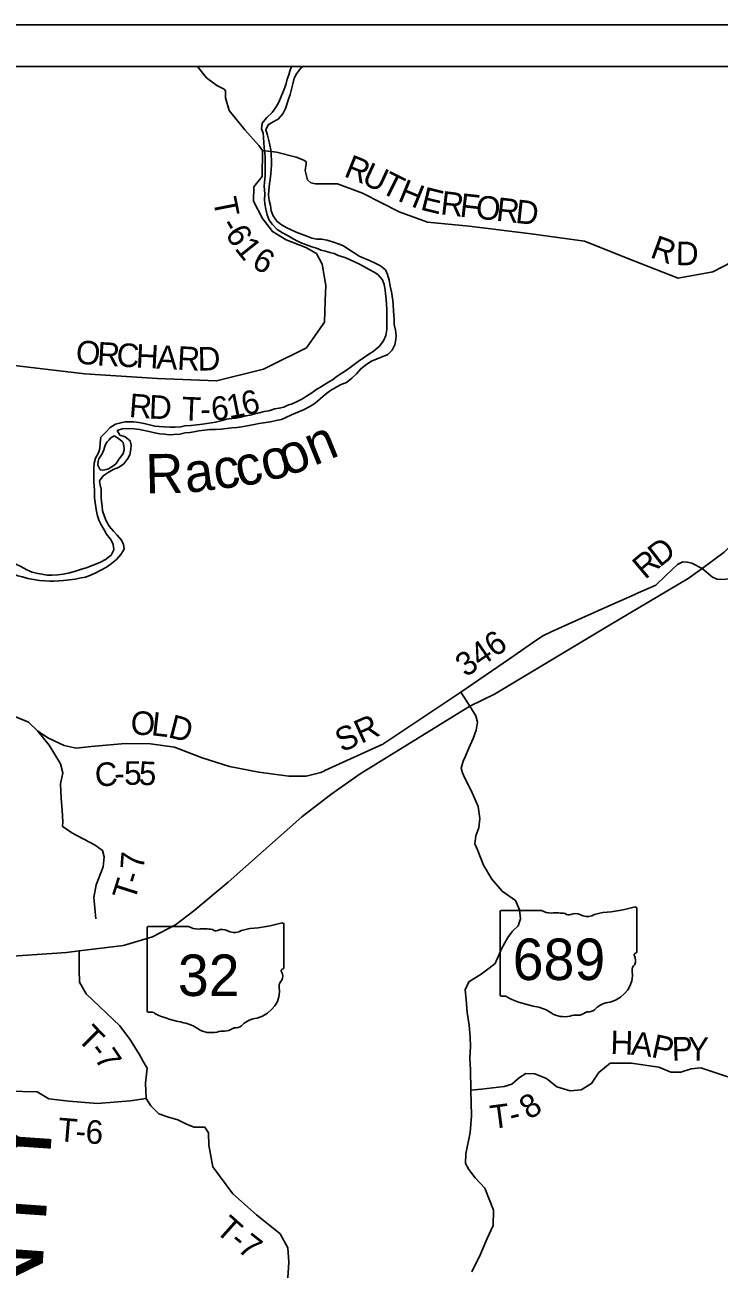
# Model space of a CAD drawing. Extents: x -15 to 405, y -40 to 87.
# Drawn here: x 1.031 to 2.706, y -21.816 to -18.816 of the extents above; entities that cross this region are included whole.
import ezdxf

# ---------------------------------------------------------------- set-up
doc = ezdxf.new("R2010")
doc.units = 0
for name, color, linetype in [('GM_P_State_Alignment', 7, 'Continuous'), ('GM_P_State_Location', 7, 'Continuous'), ('GM_X_Major_Lake_Text', 7, 'Continuous'), ('GM_X_Minor_Lake', 7, 'Continuous'), ('GM_X_Minor_River', 7, 'Continuous'), ('GM_X_State_Location', 7, 'Continuous'), ('GM_X_Township', 7, 'Continuous'), ('GM_X_Township_Road', 7, 'Continuous'), ('GM_X_Township_Road_Text', 7, 'Continuous'), ('GM_X_Township_Subdivision', 7, 'Continuous'), ('GM_X_Township_Text', 7, 'Continuous')]:
    doc.layers.add(name, color=color, linetype=linetype)

msp = doc.modelspace()

# ---------------------------------------------------------------- linework, layer by layer
at = {"layer": 'GM_P_State_Location'}
for points in [[(1.4474, -18.9161), (1.4694, -18.944), (1.4941, -18.9626), (1.5114, -18.9709), (1.5136, -18.9726), (1.5146, -18.9747), (1.5153, -18.9782), (1.5146, -18.9922), (1.5237, -19.0226), (1.5614, -19.0689), (1.5956, -19.1068), (1.6044, -19.1187), (1.6377, -19.1227), (1.6856, -19.1353), (1.7038, -19.1421), (1.7092, -19.1459), (1.7095, -19.1508), (1.7073, -19.1675), (1.713, -19.1895), (1.7208, -19.1966), (1.7323, -19.199), (1.7855, -19.199), (1.8452, -19.2221), (1.934, -19.2669), (2.0024, -19.2915), (2.1031, -19.3013), (2.2523, -19.3199), (2.3814, -19.3376), (2.5, -19.3847), (2.6071, -19.4267), (2.691, -19.4115), (2.7369, -19.3872)], [(1.7554, -19.481), (1.7554, -19.4808), (1.7568, -19.4447), (1.748, -19.3927), (1.7343, -19.3676), (1.7085, -19.3528), (1.661, -19.3342), (1.628, -19.3145), (1.6044, -19.283), (1.5824, -19.2409), (1.5831, -19.2063), (1.6036, -19.182), (1.6044, -19.1187)], [(0.9536, -19.6152), (0.9852, -19.635), (1.1759, -19.6577), (1.351, -19.6686), (1.493, -19.6742), (1.6065, -19.6464), (1.6212, -19.6391)], [(1.2021, -20.9712), (1.1972, -20.9196), (1.2032, -20.8892), (1.2199, -20.8462), (1.2225, -20.8223), (1.218, -20.8064), (1.2009, -20.7938), (1.1443, -20.7643), (1.1303, -20.7547), (1.122, -20.7487), (1.1222, -20.7377), (1.1211, -20.7096), (1.1188, -20.6815), (1.1172, -20.6458), (1.1229, -20.6196), (1.1172, -20.5976), (1.0895, -20.5528), (1.0625, -20.5186)], [(1.3135, -21.3097), (1.3133, -21.3093), (1.3064, -21.2974), (1.2855, -21.2636), (1.26, -21.229), (1.1791, -21.152), (1.1627, -21.1243), (1.1623, -21.0943), (1.1621, -21.0489)], [(1.6592, -21.9368), (1.6675, -21.7993), (1.6656, -21.7643), (1.6466, -21.7309), (1.5899, -21.6854), (1.5326, -21.6345), (1.4847, -21.5692), (1.4744, -21.5172), (1.4736, -21.4876), (1.4652, -21.4739), (1.4497, -21.4739), (1.439, -21.4739), (1.4208, -21.4667), (1.4003, -21.4557), (1.3771, -21.45), (1.354, -21.4413), (1.335, -21.4219), (1.3236, -21.4049), (1.322, -21.3673), (1.3262, -21.3316), (1.3135, -21.3097)], [(2.1066, -21.3846), (2.1328, -21.382), (2.1871, -21.3755), (2.2057, -21.3698), (2.2239, -21.3538), (2.2395, -21.3447), (2.2608, -21.3454), (2.2892, -21.356), (2.3143, -21.3762), (2.3466, -21.3864), (2.3732, -21.3841), (2.3982, -21.3681), (2.4157, -21.3419), (2.4426, -21.3191), (2.4935, -21.3195), (2.5604, -21.3293), (2.5896, -21.3411), (2.6132, -21.341), (2.6382, -21.3334), (2.6614, -21.3308), (2.7879, -21.3721)], [(0.8359, -21.4075), (0.8808, -21.4017), (0.9525, -21.3865), (1.0608, -21.3883), (1.0885, -21.4054), (1.1371, -21.4114), (1.2062, -21.4167), (1.2848, -21.4102), (1.3236, -21.4049)]]:
    msp.add_lwpolyline(points, dxfattribs=at)
at = {"layer": 'GM_X_Major_Lake_Text'}
msp.add_lwpolyline([(1.6212, -19.6391), (1.6228, -19.6383), (1.7102, -19.5947), (1.7534, -19.5328), (1.7554, -19.481)], dxfattribs=at)
at = {"layer": 'GM_X_State_Location'}
for points in [[(2.1043, -20.4588), (2.1641, -20.4294), (2.4411, -20.2634), (2.6314, -20.1512), (2.6648, -20.1267), (2.7182, -20.0876), (2.7981, -20.0074), (2.8513, -19.9357)], [(0.8594, -21.0713), (1.1313, -21.0528), (1.1621, -21.0489), (1.2686, -21.0355), (1.3387, -21.0145), (1.3944, -20.9859), (1.4388, -20.9525), (1.521, -20.8829), (1.6991, -20.7258), (1.7688, -20.6714), (1.8396, -20.6216), (2.1043, -20.4588)], [(2.0929, -20.5809), (2.0929, -20.5809), (2.1023, -20.5603), (2.1126, -20.537), (2.1199, -20.5167), (2.1232, -20.4974), (2.1188, -20.4823), (2.1043, -20.4588)], [(2.1095, -21.8225), (2.1299, -21.7798), (2.1462, -21.7424), (2.1606, -21.7111), (2.1613, -21.6739), (2.1405, -21.6209), (2.1171, -21.5961), (2.1017, -21.5758), (2.0939, -21.5611), (2.0951, -21.5379), (2.1055, -21.4869), (2.1085, -21.4467), (2.1066, -21.3846), (2.1057, -21.3358), (2.1042, -21.3062), (2.1061, -21.2789), (2.1051, -21.2565), (2.1025, -21.2277), (2.0976, -21.1973), (2.0953, -21.1659), (2.0931, -21.1427), (2.102, -21.1233), (2.1314, -21.1047), (2.151, -21.09), (2.1653, -21.0793), (2.1816, -21.0422), (2.1961, -21.0163), (2.2073, -21.0013), (2.2212, -20.9883), (2.2263, -20.9715), (2.2242, -20.9495), (2.2148, -20.9276), (2.1822, -20.9048), (2.1576, -20.8759), (2.1375, -20.8419), (2.1226, -20.8053), (2.1167, -20.7909), (2.1192, -20.7711), (2.1258, -20.7517), (2.1289, -20.7293), (2.1244, -20.7005), (2.108, -20.6623), (2.0925, -20.6325), (2.0866, -20.6193), (2.0831, -20.6079), (2.0882, -20.5912), (2.0929, -20.5809)]]:
    msp.add_lwpolyline(points, dxfattribs=at)
at = {"layer": 'GM_X_Township'}
for p, q in [((-0.7646, -18.8161), (6.2354, -18.8161)), ((-0.6646, -18.9161), (6.1354, -18.9161)), ((-0.6646, -18.9161), (6.1354, -18.9161))]:
    msp.add_line(p, q, dxfattribs=at)
at = {"layer": 'GM_X_Township_Road'}
for points in [[(1.6739, -18.9161), (1.6701, -18.9273), (1.6675, -18.9368), (1.6641, -18.9466), (1.6615, -18.9573), (1.6581, -18.9668), (1.6536, -18.9789), (1.6495, -18.9884), (1.6438, -19.0021), (1.637, -19.0138), (1.6272, -19.0275), (1.6144, -19.0397), (1.603, -19.053), (1.6019, -19.0666), (1.6061, -19.0769), (1.6069, -19.0867), (1.6073, -19.0996), (1.6085, -19.1125), (1.61, -19.125), (1.6104, -19.1348), (1.6104, -19.1474), (1.6108, -19.1599), (1.6109, -19.1803), (1.6094, -19.1951), (1.6083, -19.2046), (1.6087, -19.2141), (1.6095, -19.2239), (1.6091, -19.238), (1.6099, -19.2474), (1.6126, -19.2607), (1.6156, -19.274), (1.6202, -19.2868), (1.6274, -19.2967), (1.6399, -19.3095), (1.6525, -19.3175), (1.6661, -19.325), (1.6778, -19.3318), (1.6885, -19.3375), (1.6994, -19.3424), (1.7101, -19.3465), (1.7229, -19.3514), (1.7347, -19.3544), (1.746, -19.3589), (1.7559, -19.3615), (1.7669, -19.3645), (1.7771, -19.3675), (1.787, -19.3721), (1.8029, -19.3773), (1.8139, -19.3815), (1.826, -19.3871), (1.8362, -19.3924), (1.8487, -19.3988)], [(1.9006, -19.4066), (1.8888, -19.3972), (1.8763, -19.3904), (1.8642, -19.3847), (1.8377, -19.3734), (1.8256, -19.3655), (1.8127, -19.358), (1.7994, -19.3489), (1.7895, -19.3448), (1.7755, -19.3399), (1.76, -19.335), (1.7467, -19.3327), (1.735, -19.3324), (1.7236, -19.3305), (1.7115, -19.3253), (1.6986, -19.3207), (1.6858, -19.3155), (1.6721, -19.3094), (1.6626, -19.3053), (1.6501, -19.2985), (1.6384, -19.2894), (1.6296, -19.2762), (1.6251, -19.2645), (1.6232, -19.2516), (1.6201, -19.2395), (1.6189, -19.2266), (1.6193, -19.2148), (1.6212, -19.1996), (1.6226, -19.1886), (1.6245, -19.1754), (1.6249, -19.164), (1.6256, -19.1534), (1.626, -19.1431), (1.6252, -19.1303), (1.624, -19.1174), (1.6194, -19.0946), (1.616, -19.0818), (1.6122, -19.0693), (1.6182, -19.0567), (1.6303, -19.0499), (1.642, -19.043), (1.653, -19.0308), (1.6597, -19.0179), (1.6631, -19.0084), (1.6673, -18.9955), (1.671, -18.9838), (1.6774, -18.958), (1.6808, -18.9447), (1.6864, -18.9337), (1.6959, -18.9212), (1.7014, -18.9161)], [(1.8487, -19.3988), (1.8616, -19.4056), (1.8733, -19.412), (1.8828, -19.418), (1.8935, -19.4309), (1.898, -19.4423), (1.9003, -19.4551), (1.9011, -19.4646), (1.9023, -19.4767), (1.9034, -19.4904), (1.9038, -19.5014), (1.9042, -19.515), (1.9043, -19.5507), (1.9017, -19.5651), (1.896, -19.578), (1.8855, -19.5913), (1.8715, -19.6038), (1.8609, -19.6103), (1.8348, -19.6278), (1.822, -19.637), (1.8095, -19.6468), (1.7959, -19.6556), (1.7842, -19.6632), (1.7728, -19.672), (1.7615, -19.6784), (1.7468, -19.6876), (1.7328, -19.6963), (1.7229, -19.7032), (1.7105, -19.7116), (1.7006, -19.7177), (1.6859, -19.7253), (1.6757, -19.7299), (1.6655, -19.7333), (1.6556, -19.7379), (1.6443, -19.7398), (1.6341, -19.7421), (1.6193, -19.7463), (1.6083, -19.7486), (1.5962, -19.7513), (1.5856, -19.7536), (1.5743, -19.7567), (1.5637, -19.759), (1.5516, -19.7617), (1.5402, -19.764), (1.5304, -19.7652), (1.5175, -19.7671), (1.5066, -19.7698), (1.4907, -19.7736), (1.4801, -19.7759), (1.4702, -19.7775), (1.4596, -19.779), (1.446, -19.7802), (1.432, -19.7817), (1.4169, -19.7825), (1.407, -19.7848), (1.3934, -19.7856), (1.3809, -19.7857), (1.3677, -19.7853), (1.3548, -19.7846), (1.3446, -19.7835), (1.3317, -19.7805), (1.3184, -19.7775), (1.3056, -19.7745), (1.2927, -19.7734), (1.273, -19.7735), (1.2628, -19.7754), (1.2499, -19.7785), (1.2371, -19.7868), (1.2265, -19.7982), (1.2144, -19.8097), (1.2129, -19.8237), (1.2115, -19.8373), (1.2084, -19.8476), (1.2013, -19.8605), (1.1979, -19.873), (1.1972, -19.8855), (1.1976, -19.895), (1.1976, -19.9166), (1.198, -19.928), (1.1988, -19.9375), (1.1988, -19.9469), (1.1992, -19.9564), (1.2011, -19.9731), (1.2027, -19.9845), (1.2054, -19.9966), (1.2096, -20.0102), (1.2141, -20.0201), (1.2225, -20.0337), (1.2282, -20.0439), (1.2373, -20.056), (1.2441, -20.0677), (1.2457, -20.0818), (1.2389, -20.0943), (1.2257, -20.1053), (1.2132, -20.1111), (1.2034, -20.1156), (1.1788, -20.1252), (1.1651, -20.129), (1.1508, -20.1336), (1.1356, -20.1378), (1.1232, -20.1405)], [(1.1913, -20.1422), (1.2023, -20.1372), (1.2144, -20.1311), (1.2276, -20.1235), (1.2401, -20.1148), (1.2522, -20.1049), (1.2624, -20.0931), (1.2707, -20.0802), (1.2687, -20.0692), (1.2638, -20.0586), (1.2539, -20.0461), (1.2444, -20.037), (1.2342, -20.0249), (1.227, -20.0117), (1.2232, -20.0015), (1.2186, -19.9874), (1.2171, -19.9768), (1.2155, -19.9651), (1.2147, -19.9556), (1.2147, -19.9355), (1.2128, -19.9249), (1.2109, -19.9151), (1.2199, -19.9037), (1.232, -19.8953), (1.2441, -19.8884), (1.257, -19.8831), (1.2694, -19.8747), (1.2793, -19.8618), (1.2838, -19.8523), (1.2868, -19.8394), (1.2875, -19.8292), (1.2848, -19.8186), (1.2731, -19.8091), (1.2602, -19.805), (1.2538, -19.7944), (1.2659, -19.7902), (1.2802, -19.789), (1.295, -19.7901), (1.3075, -19.7916), (1.3192, -19.7938), (1.3442, -19.7998), (1.3564, -19.802), (1.3685, -19.8031), (1.3794, -19.8043), (1.39, -19.8035), (1.4048, -19.8027), (1.418, -19.8), (1.429, -19.7988), (1.4389, -19.7976), (1.451, -19.795), (1.4646, -19.793), (1.4775, -19.7918), (1.4907, -19.7914), (1.5043, -19.791), (1.5172, -19.7895), (1.5304, -19.7875), (1.5429, -19.7864), (1.5581, -19.784), (1.5713, -19.7821), (1.5846, -19.7798), (1.5952, -19.7775), (1.6239, -19.7729), (1.6372, -19.7702), (1.65, -19.7679), (1.6602, -19.7625), (1.6742, -19.7564), (1.6841, -19.7522), (1.7045, -19.7431), (1.7185, -19.7362), (1.7313, -19.7278), (1.7434, -19.7179), (1.7555, -19.7073), (1.7684, -19.6978), (1.782, -19.6894), (1.7937, -19.6833), (1.8065, -19.6779), (1.8194, -19.668), (1.8307, -19.6574), (1.8413, -19.6452), (1.8557, -19.6338), (1.8674, -19.6266), (1.8806, -19.6209), (1.8931, -19.6163), (1.9063, -19.6109), (1.9169, -19.6003), (1.9237, -19.5874), (1.9259, -19.5745), (1.9263, -19.565), (1.9251, -19.5525), (1.9221, -19.5385), (1.9217, -19.5256), (1.9213, -19.5161), (1.9201, -19.5059), (1.9197, -19.4907), (1.9185, -19.4805), (1.917, -19.4703), (1.9151, -19.4593), (1.912, -19.4464), (1.9094, -19.4316), (1.9055, -19.418), (1.9006, -19.4066)], [(1.2466, -19.8065), (1.2383, -19.8119), (1.2334, -19.8172), (1.2296, -19.8214), (1.2251, -19.8274), (1.2232, -19.8347), (1.2217, -19.8403), (1.2172, -19.8502), (1.2096, -19.862), (1.2077, -19.8688), (1.207, -19.8779), (1.2123, -19.8885)], [(1.2123, -19.8885), (1.2172, -19.8896), (1.2237, -19.8889), (1.2271, -19.8881), (1.2324, -19.8862), (1.2388, -19.8828), (1.2452, -19.8782), (1.2513, -19.8732), (1.2584, -19.8622), (1.2645, -19.8546), (1.2679, -19.8493), (1.2701, -19.841), (1.2705, -19.8364), (1.2678, -19.8231), (1.2655, -19.8209), (1.2572, -19.8133), (1.2466, -19.8065)], [(0.9426, -20.1187), (0.9558, -20.1277), (0.9676, -20.1322), (0.9793, -20.1341), (0.9922, -20.1367), (1.0043, -20.1408), (1.0138, -20.1446), (1.0251, -20.1472), (1.038, -20.1506), (1.0528, -20.1536), (1.0664, -20.1555), (1.0793, -20.1566), (1.091, -20.1573), (1.1009, -20.1572), (1.113, -20.1568), (1.1243, -20.1557), (1.1383, -20.1541), (1.152, -20.1526), (1.1671, -20.1495), (1.1769, -20.1476), (1.1913, -20.1422)], [(1.1232, -20.1405), (1.1107, -20.1417), (1.097, -20.1429), (1.0849, -20.1425), (1.0721, -20.1403), (1.0622, -20.1388), (1.0486, -20.1354), (1.0353, -20.1298), (1.0209, -20.1222), (1.0073, -20.1158), (0.994, -20.1105), (0.9807, -20.1057), (0.9698, -20.1017)]]:
    msp.add_lwpolyline(points, dxfattribs=at)
at = {"layer": 'GM_X_Township_Subdivision'}
for p, q in [((2.1777, -20.9546), (2.1777, -21.1547)), ((2.1777, -21.1547), (2.1777, -20.9546)), ((2.1777, -21.1547), (2.1777, -20.9546)), ((2.1809, -20.9512), (2.2774, -20.9512)), ((2.5073, -20.9462), (2.5073, -21.0509)), ((1.3262, -20.9931), (1.3262, -21.1932)), ((1.3262, -21.1932), (1.3262, -20.9931)), ((1.3262, -21.1932), (1.3262, -20.9931)), ((1.3294, -20.9897), (1.426, -20.9897)), ((1.6558, -20.9847), (1.6558, -21.0894)), ((2.5072, -21.0509), (2.5073, -21.0509)), ((1.6558, -21.0894), (1.6558, -21.0894))]:
    msp.add_line(p, q, dxfattribs=at)
for centre, major_axis, start_param, end_param in [((2.1814, -20.9542), (0.00382, 0), 1.712693, 3.28349), ((2.3004, -20.9279), (0.037, 0), 4.042523, 4.731795), ((2.3127, -21.0635), (0.133, 0), 1.404758, 1.657858), ((2.3429, -20.9532), (0.0107, 0), 3.836095, 5.185415), ((2.3586, -20.9763), (0.0222, 0), 0.950623, 2.079405), ((2.3872, -20.9446), (0.0267, 0), 4.081561, 5.145723), ((2.4344, -21.0123), (0.0703, 0), 1.699011, 2.107814), ((2.3899, -20.6783), (0.3495, 0), 4.814394, 5.042369), ((2.5036, -20.9458), (0.00367, 0), 6.141152, 7.989035), ((1.33, -20.9927), (0.00382, 0), 1.712693, 3.28349), ((1.449, -20.9664), (0.037, 0), 4.042523, 4.731795), ((1.4612, -21.102), (0.133, 0), 1.404758, 1.657858), ((1.4914, -20.9917), (0.0107, 0), 3.836095, 5.185415), ((1.5071, -21.0148), (0.0222, 0), 0.950623, 2.079405), ((1.583, -21.0508), (0.0703, 0), 1.699011, 2.107814), ((1.5384, -20.7168), (0.3495, 0), 4.814394, 5.042369), ((1.6521, -20.9843), (0.00367, 0), 6.141152, 7.989035), ((1.5358, -20.9831), (0.0267, 0), 4.081561, 5.145723), ((2.5064, -21.0586), (0.00568, 0), 1.883978, 3.671073), ((2.5033, -21.0513), (0.00393, 0), 5.05454, 6.418171), ((2.5204, -21.0947), (0.0248, 0), 2.387724, 3.262537), ((2.4703, -21.0718), (0.0341, 0), 5.934695, 6.695948), ((1.6549, -21.0971), (0.00568, 0), 1.883978, 3.671073), ((1.6188, -21.1103), (0.0341, 0), 5.934695, 6.695948), ((1.6519, -21.0898), (0.00393, 0), 5.05454, 6.418171), ((2.4094, -21.108), (0.0874, 0), 5.101752, 6.440018), ((1.558, -21.1465), (0.0874, 0), 5.101752, 6.440018), ((1.6689, -21.1332), (0.0248, 0), 2.387724, 3.262537), ((2.1815, -21.1552), (0.00385, 0), 3.00124, 4.508301), ((2.1821, -21.1347), (0.0294, 0), 4.665946, 4.897461), ((2.1881, -21.1663), (0.0106, 0), 0.519207, 1.627899), ((2.3219, -20.9865), (0.2524, 0), 4.195997, 4.488961), ((2.4463, -21.2109), (0.0479, 0), 1.647645, 2.488434), ((1.33, -21.1937), (0.00385, 0), 3.00124, 4.508301), ((1.3306, -21.1732), (0.0294, 0), 4.665946, 4.897461), ((1.3366, -21.2048), (0.0106, 0), 0.519207, 1.627899), ((1.4704, -21.025), (0.2524, 0), 4.195997, 4.488961), ((2.2467, -21.2446), (0.079, 0), 0.823519, 1.323587), ((2.3321, -21.1673), (0.0501, 0), 4.026481, 4.996735), ((2.361, -21.2365), (0.0412, 0), 1.495662, 1.94098), ((2.3647, -21.1823), (0.0267, 0), 4.691044, 5.507374), ((2.3888, -21.2016), (0.00752, 0), 1.147584, 2.315152), ((2.3856, -21.1741), (0.0282, 0), 4.937069, 5.64225), ((1.3952, -21.2831), (0.079, 0), 0.823519, 1.323587), ((1.4806, -21.2058), (0.0501, 0), 4.026481, 4.996735), ((1.5132, -21.2208), (0.0267, 0), 4.691044, 5.507374), ((1.5374, -21.2401), (0.00752, 0), 1.147584, 2.315152), ((1.5342, -21.2126), (0.0282, 0), 4.937069, 5.64225), ((1.5948, -21.2494), (0.0479, 0), 1.647645, 2.488434), ((1.5096, -21.275), (0.0412, 0), 1.495662, 1.94098)]:
    msp.add_ellipse(centre, major_axis=major_axis, ratio=0.8, start_param=start_param, end_param=end_param, dxfattribs=at)
at = {"layer": 'GM_X_Township_Text'}
for points in [[(2.5032, -20.189), (2.5532, -20.1668), (2.5767, -20.1444), (2.5931, -20.1281), (2.6055, -20.1169), (2.6181, -20.111), (2.629, -20.1112), (2.6401, -20.114), (2.6648, -20.1267), (2.6899, -20.1478), (2.7014, -20.1524), (2.7146, -20.1534), (2.7301, -20.1513), (2.7434, -20.1454), (2.7536, -20.1335), (2.7613, -20.1196), (2.7806, -20.0763), (2.792, -20.0631), (2.8061, -20.0531), (2.8296, -20.0392)], [(2.1998, -20.3443), (2.2659, -20.2987), (2.2817, -20.2885), (2.3003, -20.2791), (2.3668, -20.2501), (2.4496, -20.2128), (2.5027, -20.1892), (2.5032, -20.189)], [(1.7537, -20.6143), (1.7546, -20.6139), (1.8945, -20.55), (2.0829, -20.425), (2.1998, -20.3443)], [(2.1043, -20.4588), (2.0829, -20.425)], [(0.9043, -20.4591), (0.9692, -20.4741), (1.0071, -20.4833), (1.0393, -20.4976), (1.0625, -20.5186), (1.0883, -20.5361), (1.1259, -20.5539), (1.1544, -20.5596), (1.1912, -20.5557), (1.2729, -20.5489), (1.334, -20.5496), (1.3918, -20.5575), (1.4586, -20.5829), (1.5243, -20.6045), (1.595, -20.6174), (1.6675, -20.6272), (1.7093, -20.6272), (1.7446, -20.6184), (1.7537, -20.6143)]]:
    msp.add_lwpolyline(points, dxfattribs=at)

# ---------------------------------------------------------------- texts
at = {"layer": 'GM_P_State_Alignment'}
msp.add_text('MEIGS  COUNTY', height=0.189394, rotation=86.0177, dxfattribs=at).set_placement((0.9594, -23.4509))
at = {"layer": 'GM_X_Minor_Lake'}
for s, height, rotation, p in [('D', 0.0568, 37.9657, (2.5624, -20.1251)), ('R', 0.0568, 40.1369, (2.5272, -20.1548)), ('346', 0.05682, 34.5788, (2.0947, -20.3902)), ('O', 0.0568, 358.2366, (1.2855, -20.5272)), ('L', 0.0568, 353.666, (1.3343, -20.5287)), ('D', 0.0568, 345.4253, (1.3744, -20.533)), ('SR', 0.05682, 24.3048, (1.7956, -20.5708)), ('C', 0.0568, 4.1603, (1.2018, -20.6531)), ('5', 0.0568, 0.6922, (1.2707, -20.6485)), ('5', 0.0568, 357.194, (1.3048, -20.648)), ('-', 0.0568, 3.2959, (1.2481, -20.6498))]:
    msp.add_text(s, height=height, rotation=rotation, dxfattribs=at).set_placement(p)
at = {"layer": 'GM_X_Minor_River'}
for s, rotation, p in [('R', 338.1232, (1.7982, -19.1804)), ('U', 335.0569, (1.8407, -19.1974)), ('T', 333.3621, (1.8857, -19.2183)), ('H', 337.7328, (1.928, -19.2393)), ('T', 281.2515, (1.4845, -19.2376)), ('E', 346.2408, (1.983, -19.2611)), ('R', 353.2962, (2.0318, -19.2726)), ('F', 353.5539, (2.0784, -19.2781)), ('O', 353.5532, (2.1165, -19.2824)), ('R', 353.5503, (2.1662, -19.288)), ('D', 353.5533, (2.2126, -19.2932)), ('-', 300.7817, (1.5003, -19.2989)), ('6', 301.6939, (1.5128, -19.3198)), ('1', 308.5718, (1.5354, -19.3557)), ('R', 339.8665, (2.5369, -19.3755)), ('D', 359.4807, (2.6012, -19.3953)), ('6', 330.54, (1.5752, -19.3984)), ('O', 354.2127, (1.1516, -19.6317)), ('R', 356.8899, (1.2043, -19.637)), ('C', 356.9726, (1.251, -19.6395)), ('H', 356.9714, (1.2976, -19.642)), ('A', 356.9751, (1.3475, -19.6446)), ('R', 357.0262, (1.3975, -19.6472)), ('D', 0.8711, (1.4482, -19.6497)), ('R', 355.5657, (1.2809, -19.7612)), ('D', 357.3654, (1.3293, -19.7649)), ('1', 11.2167, (1.5237, -19.766)), ('6', 13.8962, (1.5609, -19.7586)), ('T', 357.8195, (1.4087, -19.7693)), ('6', 5.8579, (1.4832, -19.7705)), ('-', 0.499, (1.4541, -19.771)), ('7', 85.9944, (1.3178, -20.8539)), ('T', 72.4182, (1.2951, -20.9309)), ('-', 72.1575, (1.3079, -20.8905)), ('T', 314.8197, (1.1544, -21.2619)), ('H', 358.2293, (2.443, -21.2972)), ('A', 353.414, (2.4917, -21.2987)), ('P', 347.6846, (2.5399, -21.3042)), ('P', 1.5322, (2.5922, -21.3137)), ('Y', 358.7723, (2.6298, -21.3127)), ('-', 308.1502, (1.1832, -21.2907)), ('7', 304.1346, (1.197, -21.3082)), ('T', 7.5907, (2.1573, -21.4784)), ('8', 33.7197, (2.2482, -21.4573)), ('-', 14.0358, (2.2062, -21.4715)), ('T', 355.2203, (1.1087, -21.5071)), ('6', 357.0769, (1.1763, -21.5126)), ('-', 355.4995, (1.1514, -21.5107)), ('T', 318.1668, (1.488, -21.7245)), ('-', 320.2697, (1.5214, -21.7543)), ('7', 322.061, (1.5408, -21.7705))]:
    msp.add_text(s, height=0.0568, rotation=rotation, dxfattribs=at).set_placement(p)
at = {"layer": 'GM_X_Township_Road_Text'}
for s, height, rotation, p in [('on', 0.09469, 22.0989, (1.6629, -19.9063)), ('R', 0.0947, 1.1029, (1.3227, -19.9459)), ('ac', 0.0947, 7.102, (1.421, -19.945)), ('co', 0.0947, 13.1008, (1.5488, -19.9314))]:
    msp.add_text(s, height=height, rotation=rotation, dxfattribs=at).set_placement(p)
at = {"layer": 'GM_X_Township_Subdivision'}
for s, p in [('689', (2.2079, -21.119)), ('32', (1.4001, -21.1575))]:
    msp.add_text(s, height=0.1, dxfattribs=at).set_placement(p)

doc.saveas('drawing.dxf')
